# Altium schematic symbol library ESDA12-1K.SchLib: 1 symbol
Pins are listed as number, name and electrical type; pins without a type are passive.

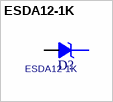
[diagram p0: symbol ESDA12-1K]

## ESDA12-1K
designator D?
footprint ST_SOD523
pins: 1 K, 2 A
